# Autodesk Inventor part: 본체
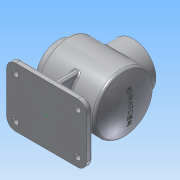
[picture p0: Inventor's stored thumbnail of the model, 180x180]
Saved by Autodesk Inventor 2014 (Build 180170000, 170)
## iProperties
Created: 2016-09
Part Number: 본체
Material: 알루미늄 6061
Document SubType Name: Modeling
Designer: 406-05
Density: 2.71 g/cm^3
Appearance: 알루미늄 - 평지
Mass: 972.342 g
Surface Area: 1283.14 cm^2
Volume: 358.798 cm^3
Author: 406-05
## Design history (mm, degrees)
sketch "스케치1"
  geometry: 1 further point
sketch "스케치2"
  geometry: L1 (-67.5, 50)-(67.5, 50); L2 (67.5, 50)-(67.5, -50); L3 (67.5, -50)-(-67.5, -50); L4 (-67.5, -50)-(-67.5, 50); 3 further points
  constraints: 8 end point, 2 midpoint, 2 parallel, 1 horizontal, 1 horizontal alignment, 1 perpendicular, 1 vertical alignment
  dimensions: "d0" = 135 distance between parallel lines of L2 L4; "d1" = 100 distance between parallel lines of L3 L1
extrude "돌출1" new body sketch "스케치2" distance "d2" = 10; taper "d3" = 0 deg
node "작업 평면1"
sketch "스케치3"
  geometry: L1 (-50, 132)-(-50, 82); L2 (-50, 82)-(60, 82); L3 (-50, 132)-(48.562, 132); L4 (0, 0)-(0, 82); L5 (46.661, 129)-(-47, 129); L6 (-47, 129)-(-47, 82); A1 r 115 centre (-55, 82) between (60, 82) and (48.562, 132); A2 r 112 centre (-55, 82) between (57, 82) and (46.661, 129)
  constraints: 12 end point, 4 point on circle, 4 point on line, 2 centre point, 2 perpendicular, 1 parallel, 1 vertical
  dimensions: "d5" = 100 diameter of L3 L2; "d6" = 110 distance of L2.end L1.end; "d7" = 115 radius of A1; "d8" = 82 distance of L4.start L4.end; "d9" = 50 distance of L4.end L1.end; "d29" = 3 distance between parallel lines of L1 L6; "d30" = 3 radial gap between concentric circles of A1 A2; "d31" = 3 distance between parallel lines of L3 L5
revolve "회전1" stored, may be unused: angle "d10" = 90 deg
node "작업 평면2"
sketch "스케치4"
  geometry: L1 (-67.5, -50)-(67.5, -50) reference; L2 (67.5, -50)-(67.5, 50) reference; L3 (67.5, 50)-(-67.5, 50) reference; L4 (-67.5, 50)-(-67.5, -50) reference; C1 r 38 at (0, 0); 1 further point
  constraints: 1 centre point, 1 coincident
  dimensions: "d12" = 76 diameter of C1
extrude "돌출2" join sketch "스케치4" distance "d13" = 65; taper "d14" = 0 deg
sketch "스케치5"
  geometry: C1 r 50 at (0, 0) reference; C2 r 38 at (0, 0); 1 further point
  constraints: 1 centre point, 1 coincident
  dimensions: "d15" = 76 diameter of C2
extrude "돌출3" join sketch "스케치5" distance "d16" = 12; taper "d17" = 0 deg
sketch "스케치6"
  geometry: L1 (-50, 32)-(48.562, 32) reference; L2 (67.5, 10)-(-67.5, 10) reference; L3 (-40, 10)-(-37.638, 37); L4 (40, 10)-(37.638, 37); L5 (-37.638, 37)-(37.638, 37); L6 (-40, 10)-(40, 10); 1 further point
  constraints: 8 end point, 2 point on line, 1 collinear, 1 parallel
  dimensions: "d18" = 40 horizontal distance of point (0, 0) L3.start; "d19" = 40 horizontal distance of L4.start point (0, 0); "d20" = 95 deg angle of L2 L3; "d21" = 95 deg angle of L2 L4; "d22" = 27 distance between parallel lines of L2 L5
extrude "돌출4" join sketch "스케치6" stored distance "d23" = 10; taper "d24" = 0 deg
node "작업 평면3"
sketch "스케치7"
  geometry: L1 (100, 10)-(0, 10) reference; L2 (10, 52)-(10, 10); L3 (90, 52)-(90, 10); A1 r 50 centre (50, 82) between (10, 52) and (90, 52) reference; 1 further point
  constraints: 4 end point, 2 point on circle, 2 point on line, 1 parallel, 1 perpendicular
  dimensions: "d25" = 40 horizontal distance of point (50, 0) L2.end; "d26" = 40 horizontal distance of point (50, 0) L3.end
extrude "돌출5" join sketch "스케치7" stored distance "d27" = 10; taper "d28" = 0 deg
revolve "회전2" stored, may be unused: angle "d32" = 90 deg
hole "구멍1" diameter "d35" = 54; stored, may be unused: countersink angle "d39" = 90 deg, drill point angle "d41" = 0 deg; dims "d33" = 10, "d34" = 10, "d36" = 6, "d37" = 4, "d38" = 2, "d40" = 15
hole "구멍2" diameter "d44" = 54; stored, may be unused: countersink angle "d48" = 90 deg, drill point angle "d50" = 0 deg; dims "d42" = 10, "d43" = 10, "d45" = 6, "d46" = 4, "d47" = 2, "d49" = 30
fillet "모깎기1" dims "d51" = 15, "d52" = 5, "d53" = 2
sketch "스케치8" dims "d54" = 65
  geometry: C1 r 27 at (0, 0) reference; 3 further points
  constraints: 2 vertical alignment, 1 coincident, 2 other
hole "구멍3" sketch "스케치8" at (0, 32.5) diameter "d55" = 3.242; stored, may be unused: countersink angle "d59" = 90 deg, drill point angle "d61" = 118 deg; dims "d56" = 8, "d57" = 4, "d58" = 2, "d60" = 10
sketch "스케치9" dims "d65" = 65
  geometry: 3 further points
  constraints: 2 vertical alignment, 1 coincident, 2 other
hole "구멍4" sketch "스케치9" at (0, 32.5) diameter "d66" = 3.242; stored, may be unused: countersink angle "d70" = 90 deg, drill point angle "d72" = 118 deg; dims "d67" = 8, "d68" = 4, "d69" = 2, "d71" = 10
hole "구멍5" diameter "d78" = 10; stored, may be unused: countersink angle "d82" = 90 deg, drill point angle "d84" = 118 deg; dims "d76" = 10, "d77" = 10, "d79" = 8, "d80" = 4, "d81" = 2, "d83" = 10
hole "구멍6" diameter "d87" = 10; stored, may be unused: countersink angle "d91" = 90 deg, drill point angle "d93" = 118 deg; dims "d85" = 10, "d86" = 10, "d88" = 8, "d89" = 4, "d90" = 2, "d92" = 10
hole "구멍7" diameter "d96" = 10; stored, may be unused: countersink angle "d100" = 90 deg, drill point angle "d102" = 118 deg; dims "d94" = 10, "d95" = 10, "d97" = 8, "d98" = 4, "d99" = 2, "d101" = 10
hole "구멍8" diameter "d105" = 10; stored, may be unused: countersink angle "d109" = 90 deg, drill point angle "d111" = 118 deg; dims "d103" = 10, "d104" = 10, "d106" = 8, "d107" = 4, "d108" = 2, "d110" = 10
fillet "모깎기2" dims "d112" = 3
fillet "모깎기3" dims "d113" = 3
chamfer "모따기1" distance "d114" = 1; stored, may be unused: second distance "d115" = 2, angle "d116" = 45 deg
chamfer "모따기2" distance "d117" = 1; stored, may be unused: second distance "d118" = 2, angle "d119" = 45 deg
node "작업 평면4"
node "작업 평면6"
  node "작업 평면5"
sketch "스케치11"
  geometry: C1 r 47.045 at (0, 0) reference; 2 further points
  constraints: 1 coincident, 1 other
extrude "돌출7" join sketch "스케치11" stored distance "d123" = 10; taper "d124" = 0 deg
sketch "스케치12"
  geometry: L1 (-55, 82)-(60.5, 82); A1 r 115 centre (-55, 82) between (49.937, 34.955) and (49.937, 129.045) reference; A2 r 115.5 centre (-55, 82) between (60.5, 82) and (50.393, 129.25); 1 further point
  constraints: 2 end point, 2 point on circle, 1 centre point, 1 horizontal
  dimensions: "d125" = 0.5 radial gap between concentric circles of A1 A2
feature "회전 곡면1" sketch "스케치12" dims angle "d127" = 90 deg
feature "분할1"
node "솔리드1"
pattern_circular "원형 패턴1" dims angle "d63" = 360 deg
pattern_circular "원형 패턴2" dims angle "d74" = 360 deg
node "투영된 루프1"
node "투영된 루프2"
node "투영된 루프3"
node "곡면1"
other parameters: "d4" = 0, "d11" = 72, "d122" = 0.5
